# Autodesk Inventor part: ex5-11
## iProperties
Shininess: 64.0
Length Units: 11272
Angle Units: 11279
Time Units: 11290
Mass Units: 11286
Length Display Precision: 3
Angle Display Precision: 2
Compacted: True
Part Number: ex5-11
Document SubType Name: Modeling
Created: 2003-11
Designer: Elise Moss
Cost Center: 0.1 lbmass
Authority: 1.92 in^3
Manufacturer: Standard
Standards Organization: Custom
Density: 0.0
Volumn: 0.0
Area: 0.0
PropertySet Name: Model Information
Control State: 0
Master: False
Checked Out: False
SaveDate: 2003-11-14
SaveTime: 19:31
TotalMass: 0.1 lbmass
TotalVolume: 1.92 in^3
Author: Elise Moss
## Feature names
1. Loft1
2. Shell1
3. Extrusion1
4. Sweep1
5. Extrusion2
6. Coil1
7. Fillet1
8. Fillet2
